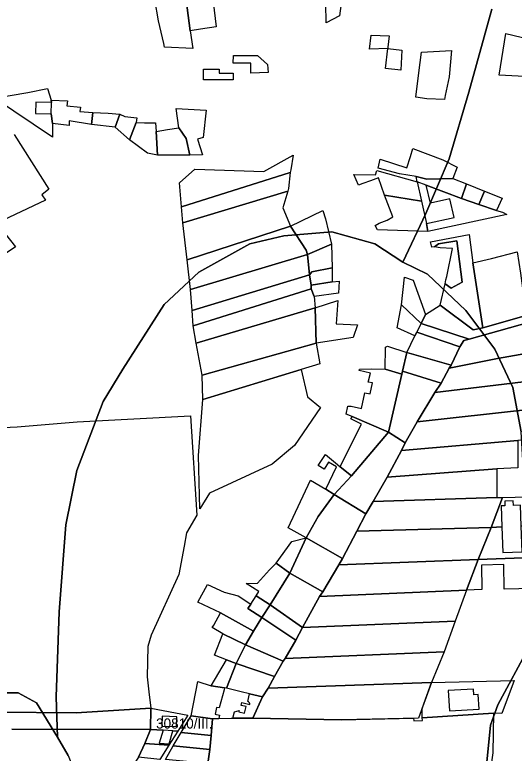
# Model space of a CAD drawing. Extents: x -532083 to -529270, y -1180561 to -1176456.
# Drawn here: x -530772.6 to -530525.7, y -1178712.9 to -1178347.7 of the extents above; entities that cross this region are included whole.
import ezdxf

# ---------------------------------------------------------------- set-up
doc = ezdxf.new("R2010")
doc.units = 0
for name, color, linetype in [('95560013', 7, 'Continuous'), ('95590013', 7, 'Continuous'), ('95610013', 7, 'Continuous'), ('95660013', 7, 'Continuous')]:
    doc.layers.add(name, color=color, linetype=linetype)

msp = doc.modelspace()

# ---------------------------------------------------------------- linework, layer by layer
at = {"layer": '95560013'}
for points in [[(-530522.6463, -1178501.05645), (-530547.9363, -1178508.08045), (-530571.6693, -1178500.40545), (-530569.5943, -1178495.85245), (-530562.2023, -1178491.29945), (-530545.9913, -1178503.52745), (-530541.1923, -1178502.48745), (-530519.7933, -1178496.37245), (-530487.1113, -1178487.26645), (-530494.1143, -1178476.72945), (-530503.0633, -1178469.05345), (-530497.2273, -1178466.84245), (-530495.8003, -1178466.32245), (-530478.8143, -1178490.47645), (-530483.0043, -1178491.58245), (-530500.0803, -1178495.72245)], [(-530512.5313, -1178513.93545), (-530533.9293, -1178517.70745), (-530557.7933, -1178522.39045), (-530556.8853, -1178520.95945), (-530552.4753, -1178511.98345), (-530550.5303, -1178508.86145), (-530547.9363, -1178508.08045), (-530522.6463, -1178501.05645), (-530500.0803, -1178495.72245), (-530483.0043, -1178491.58245), (-530480.5783, -1178508.17345), (-530490.6393, -1178510.38245), (-530492.8343, -1178498.41145), (-530503.1953, -1178500.31145), (-530500.9993, -1178512.28245)], [(-530552.4753, -1178511.98345), (-530573.7453, -1178504.69845), (-530571.6693, -1178500.40545), (-530547.9363, -1178508.08045), (-530550.5303, -1178508.86145)], [(-530523.8323, -1178558.21045), (-530581.3273, -1178563.22545), (-530579.5923, -1178559.45445), (-530573.6663, -1178549.01545), (-530518.5893, -1178542.92445), (-530518.0973, -1178557.55245)], [(-530781.7153, -1178692.62045), (-530836.3903, -1178695.78645), (-530861.8153, -1178697.61845), (-530857.3583, -1178670.82045), (-530851.9283, -1178633.59945), (-530846.3793, -1178605.97445), (-530830.6193, -1178554.28145), (-530771.3363, -1178551.46545), (-530741.6833, -1178549.05645), (-530685.6493, -1178546.03445), (-530682.6373, -1178595.14045), (-530687.7583, -1178603.90345), (-530688.8123, -1178610.55145), (-530691.4213, -1178624.48545), (-530705.1493, -1178654.45545), (-530706.7643, -1178660.12545), (-530707.1673, -1178675.11045), (-530706.3603, -1178682.60245), (-530705.2993, -1178690.54345), (-530742.1613, -1178692.82845)], [(-530534.2023, -1178572.21545), (-530588.4103, -1178576.41945), (-530581.3273, -1178563.22545), (-530523.8323, -1178558.21045), (-530523.8323, -1178571.68745)], [(-530534.2023, -1178586.42545), (-530595.3493, -1178588.45445), (-530588.4103, -1178576.41945), (-530534.2023, -1178572.21545)], [(-530541.6603, -1178631.98745), (-530549.2313, -1178632.22145), (-530543.5383, -1178617.16645), (-530503.2233, -1178615.53345), (-530509.0763, -1178631.34045), (-530530.6133, -1178631.76145), (-530530.8623, -1178619.63145), (-530541.9083, -1178619.85745)], [(-530549.2313, -1178632.22145), (-530621.8633, -1178635.33645), (-530620.3113, -1178633.08745), (-530612.3753, -1178619.76245), (-530543.5383, -1178617.16645)], [(-530554.9253, -1178647.62345), (-530630.3173, -1178650.73845), (-530621.8633, -1178635.33645), (-530549.2313, -1178632.22145)], [(-530535.8923, -1178693.13345), (-530571.0973, -1178695.43245), (-530571.2513, -1178690.74445), (-530566.4843, -1178677.90745), (-530525.7333, -1178676.95545), (-530531.8113, -1178693.21445)], [(-530557.6823, -1178691.89045), (-530543.0063, -1178691.01745), (-530543.4333, -1178683.83945), (-530545.6193, -1178683.96945), (-530545.7843, -1178681.20145), (-530558.2733, -1178681.94345)]]:
    msp.add_lwpolyline(points, close=True, dxfattribs=at)
msp.add_lwpolyline([(-530677.1223, -1178717.97145), (-530676.1083, -1178710.96645), (-530675.5453, -1178704.07345), (-530674.7573, -1178695.93845), (-530671.6583, -1178695.70845), (-530665.6463, -1178695.54945), (-530654.8103, -1178695.54945), (-530610.9943, -1178696.42445), (-530575.3773, -1178695.61245), (-530575.3393, -1178696.78545), (-530571.0573, -1178696.64445), (-530571.0973, -1178695.43245), (-530535.8923, -1178693.13345), (-530536.1813, -1178712.61545), (-530540.2403, -1178739.94945)], dxfattribs=at)
at = {"layer": '95590013'}
for points in [[(-530685.8563, -1178355.63245), (-530689.1933, -1178330.27045), (-530691.1263, -1178311.12445), (-530710.4553, -1178288.10145), (-530733.5163, -1178259.50645), (-530721.5883, -1178249.84745), (-530708.0303, -1178267.00645), (-530695.2633, -1178280.20145), (-530689.6533, -1178292.42545), (-530678.8213, -1178309.30645), (-530675.2583, -1178330.21045), (-530674.4583, -1178341.30145), (-530672.9563, -1178353.75545), (-530680.7523, -1178354.87145)], [(-530699.0993, -1178324.44745), (-530700.1893, -1178321.21245), (-530703.3653, -1178316.00945), (-530706.5463, -1178311.45645), (-530708.9753, -1178311.61845), (-530718.2023, -1178299.43945), (-530724.0303, -1178292.13245), (-530735.2273, -1178283.13245), (-530728.9683, -1178274.70145), (-530738.4123, -1178263.65045), (-530733.5163, -1178259.50645), (-530710.4553, -1178288.10145), (-530691.1263, -1178311.12445), (-530689.1933, -1178330.27045), (-530685.8563, -1178355.63245), (-530684.5543, -1178364.36245), (-530698.6143, -1178363.74445), (-530698.9373, -1178361.95845), (-530701.4593, -1178350.73345), (-530703.2593, -1178340.00845), (-530705.7373, -1178329.31845), (-530701.3663, -1178327.85745)], [(-530618.6083, -1178351.63145), (-530618.7603, -1178342.11145), (-530611.2513, -1178342.20445), (-530612.1043, -1178348.27645)], [(-530520.5053, -1178378.26645), (-530533.1183, -1178377.56345), (-530529.7583, -1178356.97945), (-530518.0533, -1178359.81645)], [(-530588.1453, -1178364.46345), (-530597.2523, -1178364.65445), (-530596.3843, -1178357.73645), (-530587.4513, -1178358.19545), (-530588.1453, -1178363.76745)], [(-530581.7233, -1178375.08445), (-530589.3613, -1178374.21445), (-530588.1453, -1178364.46345), (-530581.2023, -1178365.16045)], [(-530647.3423, -1178376.34245), (-530655.8893, -1178376.61845), (-530655.8893, -1178371.67845), (-530664.5683, -1178371.67845), (-530664.4653, -1178367.81245), (-530652.5133, -1178367.92745), (-530647.5723, -1178372.30745)], [(-530574.2313, -1178388.42845), (-530572.8603, -1178376.43345), (-530571.4723, -1178366.22045), (-530556.6633, -1178365.44645), (-530557.8973, -1178378.44545), (-530559.7683, -1178387.59145), (-530560.1853, -1178389.54445), (-530568.8073, -1178389.26545)], [(-530679.3443, -1178379.91245), (-530679.3453, -1178374.61945), (-530671.6043, -1178374.61945), (-530671.6043, -1178376.61845), (-530664.5683, -1178376.61845), (-530664.5683, -1178379.91145)], [(-530754.3903, -1178391.16345), (-530762.2323, -1178390.99745), (-530762.3493, -1178396.53545), (-530754.5083, -1178396.70145), (-530753.8493, -1178401.42745), (-530753.8493, -1178408.31845), (-530782.7093, -1178388.88145), (-530766.1333, -1178386.17945), (-530756.3943, -1178384.10145), (-530754.5293, -1178389.92145)], [(-530734.6373, -1178401.97645), (-530745.6193, -1178400.10545), (-530745.6973, -1178402.52345), (-530753.8493, -1178401.42745), (-530754.5083, -1178396.70145), (-530754.3903, -1178391.16345), (-530754.5293, -1178389.92145), (-530746.5423, -1178390.20745), (-530746.7893, -1178392.77645), (-530740.1333, -1178393.41845), (-530740.3343, -1178395.49645), (-530733.9523, -1178396.11245)], [(-530687.9013, -1178408.92245), (-530691.4583, -1178403.69145), (-530692.7693, -1178394.08445), (-530677.9453, -1178394.87445), (-530679.5013, -1178408.35145), (-530682.2063, -1178409.20745), (-530679.7863, -1178416.91945), (-530686.0503, -1178417.20545)], [(-530723.0073, -1178403.31045), (-530734.6373, -1178401.97645), (-530733.9523, -1178396.11245), (-530726.4453, -1178396.43045), (-530720.6783, -1178396.93745)], [(-530715.7813, -1178409.49045), (-530723.0073, -1178403.31045), (-530720.6783, -1178396.93745), (-530718.2283, -1178398.05045), (-530712.1863, -1178398.69045), (-530712.5823, -1178400.93345)], [(-530706.9803, -1178416.20545), (-530715.7813, -1178409.49045), (-530712.5823, -1178400.93345), (-530708.3723, -1178401.09445), (-530703.0023, -1178401.19145), (-530702.7083, -1178405.49445), (-530701.9963, -1178417.06245)], [(-530686.0503, -1178417.20545), (-530701.9963, -1178417.06245), (-530702.7083, -1178405.49445), (-530697.0993, -1178404.48145), (-530691.4583, -1178403.69145), (-530687.9013, -1178408.92245)], [(-530556.0733, -1178428.68245), (-530568.8893, -1178429.04445), (-530574.1573, -1178427.74845), (-530582.3283, -1178426.32345), (-530592.9853, -1178423.65045), (-530591.9643, -1178419.08745), (-530578.7033, -1178423.36945), (-530576.9283, -1178417.87345), (-530575.7563, -1178413.85145), (-530561.0133, -1178419.37445), (-530553.8603, -1178423.10845)], [(-530637.6333, -1178434.98445), (-530689.5433, -1178450.54045), (-530690.1083, -1178442.66845), (-530636.4563, -1178425.71845), (-530637.2023, -1178433.68845)], [(-530571.4753, -1178439.94645), (-530589.7463, -1178436.89245), (-530592.7913, -1178428.37145), (-530596.7333, -1178429.83945), (-530600.4383, -1178431.16645), (-530602.5673, -1178431.90845), (-530604.8853, -1178426.67945), (-530594.2283, -1178426.85745), (-530593.5183, -1178424.71945), (-530573.6463, -1178430.24645)], [(-530551.7743, -1178438.48945), (-530569.2533, -1178431.95245), (-530573.6463, -1178430.24645), (-530574.1573, -1178427.74845), (-530568.8893, -1178429.04445), (-530556.0733, -1178428.68245), (-530549.2713, -1178431.38345)], [(-530529.3973, -1178446.45645), (-530568.4303, -1178454.89745), (-530568.9703, -1178451.00045), (-530555.3993, -1178447.94345), (-530557.4703, -1178438.75345), (-530567.1233, -1178440.92845), (-530569.2533, -1178431.95245), (-530551.7743, -1178438.48945), (-530543.1133, -1178441.49245), (-530534.3703, -1178444.49645), (-530531.5283, -1178445.38745)], [(-530543.1133, -1178441.49245), (-530551.7743, -1178438.48945), (-530549.2713, -1178431.38345), (-530540.4123, -1178434.90245)], [(-530636.3413, -1178452.26845), (-530687.3893, -1178468.90545), (-530689.5433, -1178450.54045), (-530637.6333, -1178434.98445), (-530640.0023, -1178443.19445)], [(-530568.4303, -1178454.89745), (-530593.2723, -1178454.09345), (-530594.3943, -1178451.84345), (-530592.4993, -1178450.80945), (-530588.5303, -1178449.21645), (-530585.7393, -1178447.66345), (-530589.7463, -1178436.89245), (-530571.4753, -1178439.94645), (-530568.9703, -1178451.00045)], [(-530534.3703, -1178444.49645), (-530543.1133, -1178441.49245), (-530540.4123, -1178434.90245), (-530531.7013, -1178438.36145)], [(-530628.5873, -1178464.15145), (-530636.3413, -1178452.26845), (-530620.2263, -1178444.53345), (-530619.0003, -1178448.57645), (-530615.9673, -1178461.23145), (-530627.9403, -1178466.31245)], [(-530627.9403, -1178466.31245), (-530685.6663, -1178483.59645), (-530687.3893, -1178468.90545), (-530636.3413, -1178452.26845), (-530628.5873, -1178464.15145)], [(-530545.9913, -1178503.52745), (-530562.2023, -1178491.29945), (-530559.8433, -1178480.71545), (-530556.8813, -1178482.94345), (-530551.3283, -1178479.97245), (-530554.0433, -1178459.42445), (-530563.0523, -1178461.03345), (-530565.0263, -1178462.51845), (-530566.3453, -1178462.68845), (-530567.1243, -1178459.91945), (-530547.9343, -1178456.40745), (-530546.1033, -1178470.29945), (-530541.1923, -1178502.48745)], [(-530615.7083, -1178472.85545), (-530625.6983, -1178474.89145), (-530626.8633, -1178476.25145), (-530627.9403, -1178466.31245), (-530615.9673, -1178461.23145)], [(-530626.8633, -1178476.25145), (-530684.8043, -1178493.96745), (-530685.6663, -1178483.59645), (-530627.9403, -1178466.31245)], [(-530541.1923, -1178502.48745), (-530546.1033, -1178470.29945), (-530536.8323, -1178468.23245), (-530524.2423, -1178464.90345), (-530522.5173, -1178475.55845), (-530519.7933, -1178496.37245)], [(-530615.7083, -1178479.85745), (-530626.0023, -1178481.43645), (-530626.8633, -1178476.25145), (-530625.6983, -1178474.89145), (-530615.7083, -1178472.85545)], [(-530626.0023, -1178483.16445), (-530684.3733, -1178501.52945), (-530684.8043, -1178493.96745), (-530626.8633, -1178476.25145), (-530626.0023, -1178481.43645)], [(-530571.6693, -1178500.40545), (-530581.3473, -1178491.08745), (-530579.8473, -1178477.40945), (-530575.5523, -1178478.92945), (-530569.5943, -1178495.85245)], [(-530612.5463, -1178485.40745), (-530624.4943, -1178487.05345), (-530626.0023, -1178483.16445), (-530626.0023, -1178481.43645), (-530615.7083, -1178479.85745), (-530612.1513, -1178479.46145)], [(-530624.0633, -1178492.67145), (-530682.8663, -1178510.17145), (-530684.3733, -1178501.52945), (-530626.0023, -1178483.16445), (-530624.4943, -1178487.05345)], [(-530605.3433, -1178507.24745), (-530623.6333, -1178510.17145), (-530624.0633, -1178492.67145), (-530612.8103, -1178488.97445), (-530613.7323, -1178500.46845), (-530603.1953, -1178500.99745)], [(-530623.6333, -1178510.17145), (-530679.9743, -1178525.90145), (-530682.8663, -1178510.17145), (-530624.0633, -1178492.67145)], [(-530574.7823, -1178506.51945), (-530583.5293, -1178502.57745), (-530581.3473, -1178491.08745), (-530571.6693, -1178500.40545), (-530573.7453, -1178504.69845)], [(-530556.8853, -1178520.95945), (-530578.8023, -1178514.71545), (-530574.7823, -1178506.51945), (-530573.7453, -1178504.69845), (-530552.4753, -1178511.98345)], [(-530630.9563, -1178523.13545), (-530679.5233, -1178537.95745), (-530679.9743, -1178525.90145), (-530623.6333, -1178510.17145), (-530621.6943, -1178520.32645)], [(-530581.1823, -1178525.38045), (-530589.5403, -1178523.01145), (-530589.2563, -1178512.09945), (-530588.2993, -1178511.63345), (-530578.8023, -1178514.71545), (-530580.8773, -1178523.95145)], [(-530512.8543, -1178528.29645), (-530564.8483, -1178534.51545), (-530561.8133, -1178529.93645), (-530557.7933, -1178522.39045), (-530533.9293, -1178517.70745), (-530512.5313, -1178513.93545), (-530509.2883, -1178527.98445)], [(-530645.3563, -1178569.97245), (-530676.3203, -1178584.29245), (-530681.0263, -1178592.06245), (-530681.7773, -1178565.68845), (-530679.5233, -1178537.95745), (-530630.9563, -1178523.13545), (-530627.8623, -1178536.69445), (-530621.4283, -1178541.93745), (-530634.2973, -1178560.69445)], [(-530587.8323, -1178554.08945), (-530605.7453, -1178546.37545), (-530608.7613, -1178545.16445), (-530607.8933, -1178541.20845), (-530606.2893, -1178541.23545), (-530601.1833, -1178542.36645), (-530599.4753, -1178534.65445), (-530596.9603, -1178535.21245), (-530595.7613, -1178529.80345), (-530597.7893, -1178529.35445), (-530596.7963, -1178524.87345), (-530602.3903, -1178523.63445), (-530602.2323, -1178522.94645), (-530596.3643, -1178522.83445), (-530589.5403, -1178523.01145), (-530581.1823, -1178525.38045)], [(-530579.5923, -1178559.45445), (-530587.8323, -1178554.08945), (-530581.1823, -1178525.38045), (-530580.8773, -1178523.95145), (-530561.8133, -1178529.93645), (-530564.8483, -1178534.51545), (-530573.6663, -1178549.01545)], [(-530518.5893, -1178542.92445), (-530573.6663, -1178549.01545), (-530564.8483, -1178534.51545), (-530512.8543, -1178528.29645), (-530512.6903, -1178542.43145)], [(-530587.8323, -1178554.08945), (-530606.1903, -1178575.69445), (-530611.7773, -1178571.18245), (-530610.1203, -1178567.77445), (-530601.1993, -1178550.19145), (-530606.4383, -1178547.53345), (-530605.7453, -1178546.37545)], [(-530598.9623, -1178594.54445), (-530614.7193, -1178584.97445), (-530606.1903, -1178575.69445), (-530587.8323, -1178554.08945), (-530579.5923, -1178559.45445), (-530581.3273, -1178563.22545), (-530588.4103, -1178576.41945), (-530595.3493, -1178588.45445)], [(-530614.7193, -1178584.97445), (-530618.7283, -1178582.37445), (-530613.5633, -1178571.22845), (-530617.4763, -1178568.87345), (-530619.6673, -1178572.48445), (-530622.6403, -1178570.60045), (-530619.0153, -1178565.13245), (-530612.9833, -1178570.17445), (-530611.7773, -1178571.18245), (-530606.1903, -1178575.69445)], [(-530628.5963, -1178606.28945), (-530637.3773, -1178601.45945), (-530626.3973, -1178577.82145), (-530618.7283, -1178582.37445), (-530614.7193, -1178584.97445), (-530622.5253, -1178595.84945)], [(-530610.5273, -1178616.58445), (-530628.5963, -1178606.28945), (-530622.5253, -1178595.84945), (-530614.7193, -1178584.97445), (-530598.9623, -1178594.54445), (-530603.4443, -1178603.09945)], [(-530537.0943, -1178601.21445), (-530603.4443, -1178603.09945), (-530598.9623, -1178594.54445), (-530595.3493, -1178588.45445), (-530534.2023, -1178586.42545), (-530531.4563, -1178586.42545)], [(-530531.7413, -1178601.00845), (-530537.0943, -1178601.21445), (-530531.4563, -1178586.42545), (-530493.9933, -1178585.49945), (-530491.7423, -1178585.49945), (-530495.5693, -1178594.98345), (-530497.3703, -1178600.17745), (-530522.1603, -1178600.66945), (-530522.5303, -1178590.21645), (-530526.1023, -1178590.34345), (-530526.1663, -1178588.02745), (-530530.2803, -1178588.20745), (-530530.2873, -1178590.49145), (-530532.1113, -1178590.55545)], [(-530543.5383, -1178617.16645), (-530612.3753, -1178619.76245), (-530610.5273, -1178616.58445), (-530603.4443, -1178603.09945), (-530537.0943, -1178601.21445)], [(-530503.2233, -1178615.53345), (-530543.5383, -1178617.16645), (-530537.0943, -1178601.21445), (-530531.7413, -1178601.00845), (-530531.2963, -1178613.55545), (-530521.7163, -1178613.21645), (-530522.1603, -1178600.66945), (-530497.3703, -1178600.17745)], [(-530636.6463, -1178623.83045), (-530643.2853, -1178618.83545), (-530635.6083, -1178608.22145), (-530628.5963, -1178606.28945)], [(-530620.3113, -1178633.08745), (-530636.6463, -1178623.83045), (-530628.5963, -1178606.28945), (-530610.5273, -1178616.58445), (-530612.3753, -1178619.76245)], [(-530636.6463, -1178623.83045), (-530646.3623, -1178639.44245), (-530653.2443, -1178634.99545), (-530651.8963, -1178632.90945), (-530658.1403, -1178628.87445), (-530652.5373, -1178628.72445), (-530646.6683, -1178622.23845), (-530643.2853, -1178618.83545)], [(-530630.3173, -1178650.73845), (-530646.3623, -1178639.44245), (-530636.6463, -1178623.83045), (-530620.3113, -1178633.08745), (-530621.8633, -1178635.33645)], [(-530654.4893, -1178652.55045), (-530670.8803, -1178643.39345), (-530682.0843, -1178638.19045), (-530677.3113, -1178629.44945), (-530669.0123, -1178633.19545), (-530662.1753, -1178635.11845), (-530655.9313, -1178639.15345), (-530657.3723, -1178641.38445), (-530650.4903, -1178645.83145)], [(-530650.4903, -1178645.83145), (-530657.3723, -1178641.38445), (-530655.9313, -1178639.15345), (-530653.2443, -1178634.99545), (-530646.3623, -1178639.44245)], [(-530633.5953, -1178656.96845), (-530650.4903, -1178645.83145), (-530646.3623, -1178639.44245), (-530630.3173, -1178650.73845)], [(-530658.4313, -1178659.21045), (-530669.6353, -1178653.79945), (-530675.0293, -1178650.67745), (-530674.1993, -1178649.63645), (-530670.8803, -1178643.39345), (-530654.4893, -1178652.55045)], [(-530639.8603, -1178667.38345), (-530658.4313, -1178659.21045), (-530654.4893, -1178652.55045), (-530650.4903, -1178645.83145), (-530633.5953, -1178656.96845), (-530638.9433, -1178665.96745)], [(-530560.2733, -1178662.67945), (-530638.9433, -1178665.96745), (-530633.5953, -1178656.96845), (-530630.3173, -1178650.73845), (-530554.9253, -1178647.62345)], [(-530663.2033, -1178668.57545), (-530667.9753, -1178666.70245), (-530673.8763, -1178664.43745), (-530669.6353, -1178653.79945), (-530658.4313, -1178659.21045)], [(-530644.1323, -1178675.00045), (-530663.2033, -1178668.57545), (-530658.4313, -1178659.21045), (-530639.8603, -1178667.38345)], [(-530566.4843, -1178677.90745), (-530647.3753, -1178680.79245), (-530644.1323, -1178675.00045), (-530639.8603, -1178667.38345), (-530638.9433, -1178665.96745), (-530560.2733, -1178662.67945)], [(-530668.8893, -1178680.47545), (-530675.4443, -1178679.60645), (-530667.9753, -1178666.70245), (-530663.2033, -1178668.57545), (-530667.9403, -1178680.71345)], [(-530644.1323, -1178675.00045), (-530647.3753, -1178680.79245), (-530650.1433, -1178684.99745), (-530656.5673, -1178683.43545), (-530660.5843, -1178682.45845), (-530667.9403, -1178680.71345), (-530663.2033, -1178668.57545)], [(-530674.7573, -1178695.93845), (-530685.3453, -1178694.46945), (-530682.0783, -1178677.40845), (-530675.4443, -1178679.60645), (-530668.8893, -1178680.47545), (-530669.0953, -1178681.61045), (-530669.1213, -1178681.60545), (-530671.5903, -1178690.46645), (-530672.7933, -1178690.24445), (-530673.5853, -1178693.56745), (-530671.3593, -1178694.06645), (-530671.6583, -1178695.70845)], [(-530566.4843, -1178677.90745), (-530573.0393, -1178695.55945), (-530610.9943, -1178696.42445), (-530654.8103, -1178695.54945), (-530650.1433, -1178684.99745), (-530647.3753, -1178680.79245)], [(-530650.1433, -1178684.99745), (-530654.8103, -1178695.54945), (-530664.7533, -1178695.54945), (-530663.9613, -1178692.39645), (-530661.5873, -1178691.73245), (-530661.7773, -1178692.36545), (-530659.0233, -1178692.99745), (-530658.2633, -1178689.76945), (-530660.6693, -1178689.26345), (-530660.3213, -1178687.77645), (-530656.3513, -1178688.73945), (-530656.3633, -1178688.59045), (-530656.3883, -1178688.44445), (-530656.4263, -1178688.30045), (-530656.4763, -1178688.16045), (-530656.5383, -1178688.02445), (-530656.6113, -1178687.89545), (-530656.6953, -1178687.77245), (-530656.7903, -1178687.65745), (-530656.8943, -1178687.55045), (-530657.0063, -1178687.45345), (-530657.1273, -1178687.36645), (-530657.2553, -1178687.29045), (-530657.3893, -1178687.22545), (-530656.5673, -1178683.43545)], [(-530705.5063, -1178701.13745), (-530705.2993, -1178690.54345), (-530687.0343, -1178694.01745), (-530691.9913, -1178702.03945), (-530694.4893, -1178701.83445), (-530699.1993, -1178701.43245)], [(-530692.4813, -1178694.82745), (-530699.6963, -1178694.52545), (-530699.9013, -1178699.42145), (-530692.6863, -1178699.72345)], [(-530675.5453, -1178704.07345), (-530690.3013, -1178702.60445), (-530685.3453, -1178694.46945), (-530674.7573, -1178695.93845)], [(-530696.3843, -1178708.93245), (-530708.3233, -1178708.14145), (-530705.5063, -1178701.13745), (-530699.1993, -1178701.43245), (-530701.2033, -1178707.86545), (-530696.2933, -1178708.16645), (-530694.4893, -1178701.83445), (-530691.9913, -1178702.03945)], [(-530676.1083, -1178710.96645), (-530694.2433, -1178709.15845), (-530690.3013, -1178702.60445), (-530675.5453, -1178704.07345)], [(-530700.8893, -1178716.05045), (-530711.4773, -1178714.80745), (-530708.3233, -1178708.14145), (-530696.3843, -1178708.93245)], [(-530677.1223, -1178717.97145), (-530698.0733, -1178716.05045), (-530694.2433, -1178709.15845), (-530676.1083, -1178710.96645)]]:
    msp.add_lwpolyline(points, close=True, dxfattribs=at)
msp.add_lwpolyline([(-530772.8193, -1178406.84045), (-530755.7193, -1178434.03445), (-530759.2643, -1178436.75345), (-530757.3873, -1178439.47245), (-530781.5773, -1178450.76845), (-530772.1933, -1178462.48245), (-530790.2553, -1178474.42845)], dxfattribs=at)
at = {"layer": '95610013'}
for points in [[(-530636.4563, -1178425.71845), (-530690.1083, -1178442.66845), (-530691.0933, -1178430.80345), (-530683.6303, -1178424.02345), (-530649.4113, -1178425.15345), (-530634.9073, -1178417.10145), (-530636.0333, -1178424.44745)], [(-530556.8813, -1178482.94345), (-530559.8433, -1178480.71545), (-530559.4733, -1178478.73545), (-530559.0043, -1178477.14745), (-530556.2013, -1178463.35745), (-530562.3413, -1178462.95645), (-530565.0263, -1178462.51845), (-530563.0523, -1178461.03345), (-530554.0433, -1178459.42445), (-530551.3283, -1178479.97245)], [(-530561.8133, -1178529.93645), (-530580.8773, -1178523.95145), (-530578.8023, -1178514.71545), (-530556.8853, -1178520.95945), (-530557.7933, -1178522.39045)]]:
    msp.add_lwpolyline(points, close=True, dxfattribs=at)
for points in [[(-530781.7153, -1178692.62045), (-530742.1613, -1178692.82845), (-530705.2993, -1178690.54345), (-530705.5063, -1178701.13745), (-530774.0523, -1178700.92945)], [(-530774.0523, -1178700.92945), (-530705.5063, -1178701.13745), (-530708.3233, -1178708.14145), (-530711.4773, -1178714.80745), (-530715.9833, -1178721.81245), (-530720.7143, -1178730.17345), (-530725.7083, -1178738.78045), (-530730.1623, -1178745.99845), (-530732.9033, -1178753.56045), (-530735.6443, -1178760.94945), (-530738.3863, -1178769.02645), (-530740.6133, -1178776.58845), (-530742.6203, -1178784.04045), (-530744.6043, -1178792.23545), (-530744.9543, -1178800.78245), (-530747.6393, -1178808.15745), (-530749.5063, -1178816.00145), (-530750.7903, -1178823.26045), (-530753.4283, -1178832.35745), (-530829.5283, -1178843.57645)]]:
    msp.add_lwpolyline(points, dxfattribs=at)
at = {"layer": '95660013'}
for points in [[(-530536.6873, -1178345.00045), (-530548.1253, -1178386.00045), (-530557.8753, -1178419.00045), (-530569.3753, -1178446.00045), (-530580.8123, -1178470.00045), (-530594.6253, -1178461.00045), (-530615.8753, -1178455.00045), (-530639.6253, -1178457.00045), (-530656.3123, -1178461.00045), (-530681.6253, -1178475.00045), (-530698.6873, -1178491.00045), (-530719.1253, -1178523.00045), (-530728.8753, -1178539.00045), (-530741.8753, -1178573.00045), (-530747.3123, -1178600.00045), (-530750.6253, -1178643.00045), (-530752.1873, -1178685.00045), (-530751.3753, -1178705.00045), (-530761.8753, -1178688.00045), (-530770.8753, -1178683.00045), (-530783.1873, -1178683.00045)], [(-530482.3753, -1179007.00045), (-530459.3753, -1178970.00045), (-530450.0003, -1178942.00045), (-530444.3123, -1178914.00045), (-530439.3753, -1178865.00045), (-530435.6873, -1178792.00045), (-530441.3753, -1178755.00045), (-530458.6253, -1178702.00045), (-530468.8753, -1178678.00045), (-530500.8753, -1178629.00045), (-530509.1253, -1178619.00045), (-530516.1253, -1178612.00045), (-530518.8753, -1178610.00045), (-530522.1873, -1178554.00045), (-530526.3123, -1178532.00045), (-530535.3123, -1178513.00045), (-530549.6253, -1178494.00045), (-530568.5003, -1178476.00045), (-530580.8123, -1178470.00045), (-530569.3753, -1178446.00045), (-530557.8753, -1178419.00045), (-530548.1253, -1178386.00045), (-530536.6873, -1178345.00045)], [(-530746.1253, -1178714.00045), (-530751.3753, -1178705.00045), (-530752.1873, -1178685.00045), (-530750.6253, -1178643.00045), (-530747.3123, -1178600.00045), (-530741.8753, -1178573.00045), (-530728.8753, -1178539.00045), (-530719.1253, -1178523.00045), (-530698.6873, -1178491.00045), (-530681.6253, -1178475.00045), (-530656.3123, -1178461.00045), (-530639.6253, -1178457.00045), (-530615.8753, -1178455.00045), (-530594.6253, -1178461.00045), (-530580.8123, -1178470.00045), (-530568.5003, -1178476.00045), (-530549.6253, -1178494.00045), (-530535.3123, -1178513.00045), (-530526.3123, -1178532.00045), (-530522.1873, -1178554.00045)], [(-530680.6253, -1178987.00045), (-530659.1873, -1178976.00045), (-530623.1253, -1178960.00045), (-530580.1253, -1178909.00045), (-530563.6873, -1178878.00045), (-530559.6253, -1178861.00045), (-530549.8123, -1178813.00045), (-530541.6253, -1178742.00045), (-530537.3753, -1178699.00045), (-530533.8123, -1178689.00045), (-530518.1873, -1178660.00045), (-530517.3753, -1178651.00045), (-530516.1253, -1178612.00045), (-530509.1253, -1178619.00045), (-530500.8753, -1178629.00045), (-530468.8753, -1178678.00045), (-530458.6253, -1178702.00045), (-530441.3753, -1178755.00045), (-530435.6873, -1178792.00045), (-530439.3753, -1178865.00045), (-530444.3123, -1178914.00045), (-530450.0003, -1178942.00045), (-530459.3753, -1178970.00045), (-530482.3753, -1179007.00045)], [(-530518.1873, -1178660.00045), (-530533.8123, -1178689.00045), (-530537.3753, -1178699.00045), (-530541.6253, -1178742.00045)], [(-530783.1873, -1178683.00045), (-530770.8753, -1178683.00045), (-530761.8753, -1178688.00045), (-530751.3753, -1178705.00045), (-530746.1253, -1178714.00045), (-530736.3123, -1178739.00045), (-530724.8123, -1178779.00045), (-530723.1873, -1178806.00045), (-530728.1253, -1178828.00045), (-530734.6873, -1178836.00045), (-530751.5003, -1178849.00045), (-530769.5003, -1178856.00045), (-530793.3123, -1178881.00045)]]:
    msp.add_lwpolyline(points, dxfattribs=at)

# ---------------------------------------------------------------- texts
msp.add_text('30810/III.', height=5, rotation=359.9999999, dxfattribs=at).set_placement((-530702.7188, -1178700.66703))

doc.saveas('drawing.dxf')
